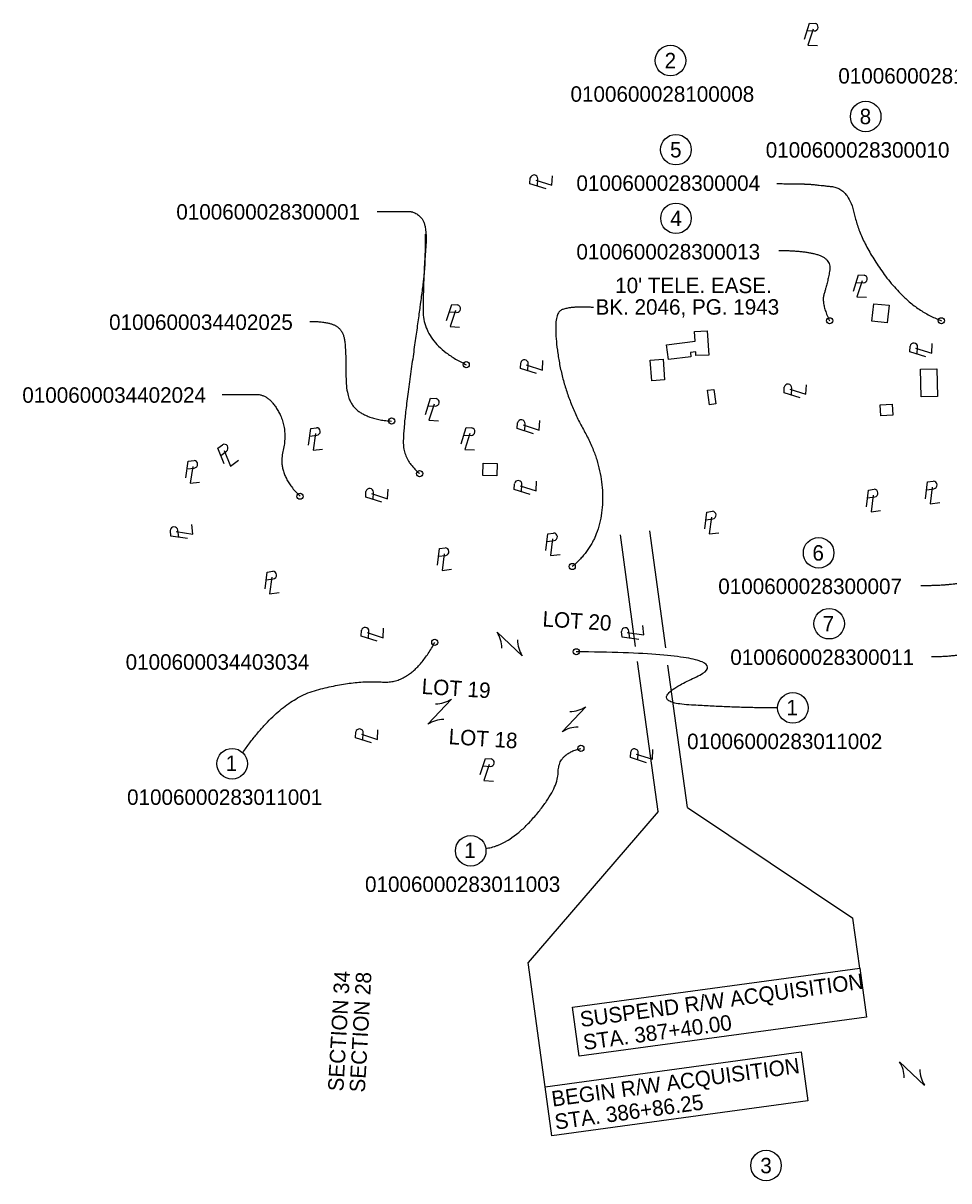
# Model space of a CAD drawing. Extents: x 1571291 to 1576333, y 700252 to 704384.
# Drawn here: x 1571291 to 1572970, y 701776 to 703874 of the extents above; entities that cross this region are included whole.
import ezdxf

# ---------------------------------------------------------------- set-up
doc = ezdxf.new("R2010")
doc.units = 0
doc.layers.add('RW_X_CL_100_Bearings', color=7, linetype='Continuous')
doc.layers.add('RW_X_CL_100_Cardinal_Points', color=7, linetype='Continuous')

msp = doc.modelspace()

# ---------------------------------------------------------------- linework, layer by layer
at = {"layer": 'RW_X_CL_100_Bearings'}
for p, q in [((1572402, 702743.9), (1572374.4, 702946.3)), ((1572456.6, 702741.8), (1572427.7, 702953.6)), ((1572442.7, 702445.1), (1572405.7, 702717)), ((1572496, 702452.4), (1572460.8, 702710.4)), ((1572442.7, 702445.1), (1572207.3, 702171.3)), ((1572496, 702452.4), (1572796.1, 702251.5)), ((1572808.5, 702161.1), (1572796.1, 702251.5)), ((1572238, 701946.1), (1572207.3, 702171.3))]:
    msp.add_line(p, q, dxfattribs=at)
for points in [[(1572830.8, 703333.7), (1572833.9, 703365.6), (1572861.7, 703362.9), (1572858.6, 703330.9)], [(1572461.9, 703264.3), (1572458.3, 703290.7), (1572509.8, 703297.8), (1572508.9, 703314.9), (1572531.9, 703316.5), (1572534.9, 703272.1), (1572511.5, 703271.8), (1572511.5, 703278.4), (1572501.4, 703277.2), (1572502.4, 703269.3)], [(1572431.6, 703226), (1572428.7, 703262.9), (1572451.8, 703264.7), (1572454.7, 703227.8)], [(1572919, 703246.9), (1572948.3, 703247.7), (1572949.6, 703197.4), (1572920.2, 703196.7)], [(1572532.4, 703208.7), (1572544.1, 703210.3), (1572547.7, 703183.8), (1572536, 703182.3)], [(1572846.8, 703162), (1572845.4, 703182.1), (1572867.5, 703183.6), (1572868.8, 703163.5)], [(1572150.4, 703053.5), (1572125.2, 703054.2), (1572125.8, 703076.6), (1572151, 703075.9)], [(1572125.8, 703076.6), (1572151, 703075.9), (1572150.4, 703053.5), (1572125.2, 703054.2)], [(1572287.7, 702090.2), (1572808.5, 702161.1), (1572820.6, 702072.4), (1572299.8, 702001.5)], [(1572238, 701946.1), (1572702.6, 702009.5), (1572714.7, 701920.8), (1572250.1, 701857.5)]]:
    msp.add_lwpolyline(points, close=True, dxfattribs=at)
for centre, radius in [((1572465.2, 703806.2), 27.7), ((1572819.4, 703704.9), 27.7), ((1572475.2, 703644.7), 27.7), ((1572475.3, 703520.3), 27.7), ((1572754, 703334.6), 5.6), ((1572956.7, 703334.6), 5.6), ((1572094.8, 703254.9), 5.6), ((1571959.5, 703152.9), 5.6), ((1572010.3, 703057.6), 5.6), ((1571793.5, 703016.6), 5.6), ((1572734, 702913.9), 27.7), ((1572287.1, 702889.2), 5.6), ((1572753.1, 702785.5), 27.7), ((1572037.8, 702751.7), 5.6), ((1572294.5, 702734.6), 5.6), ((1572687.3, 702632.8), 27.7), ((1572302.8, 702559.5), 5.6), ((1571670.2, 702531.7), 27.7), ((1572103, 702373.9), 27.7), ((1572638.6, 701803.3), 27.7)]:
    msp.add_circle(centre, radius, dxfattribs=at)
for points in [[(1572658.5, 703583.2), (1572706, 703582.9), (1572728.4, 703581.3), (1572789.1, 703574.2), (1572809.5, 703477.8), (1572899.4, 703355.8), (1572956.7, 703334.6)], [(1571933.3, 703532.6), (1571978.4, 703532.6), (1572003.9, 703532.6), (1572025, 703506.3), (1572016.7, 703413.1), (1572016.7, 703292.2), (1572094.8, 703254.9)], [(1572020.4, 703491.3), (1572020.2, 703451.5), (1572018.7, 703416.2), (1572003.9, 703309.4), (1571980.7, 703144.1), (1571980.7, 703082.5), (1572010.3, 703057.6)], [(1572661.7, 703462.1), (1572707.1, 703462.1), (1572758, 703446.5), (1572749.4, 703400.3), (1572738.3, 703366), (1572754, 703334.6)], [(1572325.6, 703358.7), (1572284, 703361.4), (1572250.6, 703346.7), (1572271.8, 703200.6), (1572345.8, 703069.2), (1572337.6, 702930.7), (1572287.1, 702889.2)], [(1571811, 703333.4), (1571845.6, 703333.4), (1571872.5, 703316.5), (1571876.8, 703276.1), (1571876.8, 703185.7), (1571923.9, 703154.4), (1571959.5, 703152.9)], [(1571652.4, 703201), (1571692.1, 703201), (1571737.3, 703201), (1571772.1, 703137.9), (1571752.4, 703055.6), (1571793.5, 703016.6)], [(1572939, 702725.9), (1572983.1, 702725.9), (1573049.4, 702743.7), (1573053.8, 702812.4), (1573062.7, 702941.2), (1573128.7, 703089.5), (1573148.7, 703138.8)], [(1572919.6, 702854.8), (1572979.9, 702854.8), (1573023.3, 702870.6), (1573035.2, 702906.9), (1573010.7, 703093.5), (1573044.7, 703124.2)], [(1571689.4, 702551.7), (1571755.6, 702646.5), (1571889.6, 702683.5), (1571997.2, 702676), (1572037.8, 702751.7)], [(1572659.6, 702632.8), (1572589.6, 702632.8), (1572411.5, 702643.6), (1572607.2, 702731.8), (1572294.5, 702734.6)], [(1572130.4, 702378.1), (1572173.8, 702384.1), (1572261.8, 702485.3), (1572261.8, 702549.7), (1572302.8, 702559.5)]]:
    msp.add_open_spline(points, degree=2, dxfattribs=at)
at = {"layer": 'RW_X_CL_100_Cardinal_Points'}
for p, q in [((1572713, 703860.5), (1572725.9, 703860)), ((1572720.7, 703853.9), (1572720.7, 703853.9)), ((1572223.9, 703578.8), (1572224.6, 703591.7)), ((1572230.6, 703586.5), (1572230.6, 703586.5)), ((1572802, 703404.2), (1572814.9, 703403.6)), ((1572809.7, 703397.6), (1572809.7, 703397.6)), ((1572064.5, 703350.7), (1572077.4, 703349.9)), ((1572072.1, 703344), (1572072.1, 703344)), ((1572912.9, 703274.1), (1572913.5, 703287.1)), ((1572919.5, 703281.9), (1572919.5, 703281.9)), ((1572206.6, 703243.8), (1572207.3, 703256.8)), ((1572213.2, 703251.5), (1572213.2, 703251.5)), ((1572684.8, 703199.6), (1572685.3, 703212.5)), ((1572691.3, 703207.3), (1572691.3, 703207.3)), ((1572025.7, 703180.6), (1572038.7, 703180)), ((1572033.4, 703174), (1572033.4, 703174)), ((1572201, 703134.9), (1572201.6, 703147.8)), ((1572207.6, 703142.6), (1572207.6, 703142.6)), ((1571811.1, 703125.5), (1571824, 703127.1)), ((1571819.9, 703120.3), (1571819.9, 703120.3)), ((1572090.6, 703127.5), (1572103.5, 703126.9)), ((1572098.3, 703120.9), (1572098.3, 703120.9)), ((1571649.6, 703090.6), (1571660, 703098.4)), ((1571659.7, 703090.4), (1571659.7, 703090.4)), ((1571588.6, 703066.3), (1571601.5, 703067.6)), ((1571597.2, 703060.9), (1571597.2, 703060.9)), ((1571926, 703010.7), (1571926.7, 703023.7)), ((1572195.3, 703024.7), (1572195.9, 703037.7)), ((1572201.9, 703032.4), (1572201.9, 703032.4)), ((1572930, 703028.3), (1572942.8, 703030.1)), ((1571932.7, 703018.4), (1571932.7, 703018.4)), ((1572822.8, 703013.7), (1572835.7, 703015.5)), ((1572831.6, 703008.6), (1572831.6, 703008.6)), ((1572938.8, 703023.2), (1572938.8, 703023.2)), ((1572529.4, 702973.7), (1572542.2, 702975.5)), ((1572538.2, 702968.6), (1572538.2, 702968.6)), ((1571573.3, 702942.1), (1571571.9, 702955)), ((1571578.6, 702950.8), (1571578.6, 702950.8)), ((1572241.4, 702934.5), (1572254.2, 702936.2)), ((1572250.2, 702929.4), (1572250.2, 702929.4)), ((1572044.7, 702907.7), (1572057.5, 702909.4)), ((1572053.5, 702902.6), (1572053.5, 702902.6)), ((1571732.1, 702865), (1571744.9, 702866.8)), ((1571740.8, 702860), (1571740.8, 702860)), ((1571917.6, 702758.8), (1571918.4, 702771.7)), ((1572391.5, 702759.3), (1572390, 702772.1)), ((1571924.3, 702766.4), (1571924.3, 702766.4)), ((1572196.4, 702727.5), (1572150.7, 702770.1)), ((1572396.8, 702768), (1572396.8, 702768)), ((1572173.5, 702748.8), (1572173.5, 702748.8)), ((1572025.4, 702603.1), (1572068, 702648.8)), ((1572046.7, 702625.9), (1572046.7, 702625.9)), ((1572269, 702589.5), (1572311.6, 702635.1)), ((1572290.3, 702612.3), (1572290.3, 702612.3)), ((1571907.3, 702574.5), (1571908.1, 702587.5)), ((1571914, 702582.2), (1571914, 702582.2)), ((1572406.1, 702538.5), (1572406.8, 702551.4)), ((1572412.8, 702546.1), (1572412.8, 702546.1)), ((1572125.5, 702527.6), (1572138.5, 702526.9)), ((1572133.2, 702520.9), (1572133.2, 702520.9)), ((1572926.3, 701948.7), (1572880.7, 701991.4)), ((1572903.5, 701970.1), (1572903.5, 701970.1))]:
    msp.add_line(p, q, dxfattribs=at)
for points in [[(1572708.1, 703844.8), (1572717.2, 703874.1), (1572727.5, 703873.6)], [(1572723.8, 703863.4), (1572714.7, 703834.2), (1572732.1, 703833.5)], [(1572239.6, 703573.8), (1572210.4, 703583.1), (1572210.9, 703593.4)], [(1572221.1, 703589.6), (1572250.2, 703580.2), (1572251.1, 703597.6)], [(1572797.1, 703388.5), (1572806.2, 703417.8), (1572816.5, 703417.3)], [(1572812.8, 703407.1), (1572803.6, 703377.9), (1572821, 703377.1)], [(1572059.2, 703335.1), (1572069, 703364.2), (1572079.3, 703363.5)], [(1572075.4, 703353.4), (1572065.5, 703324.4), (1572082.9, 703323.2)], [(1572928.6, 703269.2), (1572899.3, 703278.4), (1572899.8, 703288.7)], [(1572910, 703285), (1572939.2, 703275.7), (1572940, 703293.2)], [(1572222.3, 703238.8), (1572193.1, 703248.1), (1572193.6, 703258.4)], [(1572203.8, 703254.7), (1572232.9, 703245.2), (1572233.8, 703262.7)], [(1572700.5, 703194.7), (1572671.2, 703203.8), (1572671.6, 703214.1)], [(1572681.8, 703210.4), (1572711.1, 703201.3), (1572711.8, 703218.7)], [(1572020.8, 703164.9), (1572030, 703194.1), (1572040.3, 703193.6)], [(1572036.5, 703183.5), (1572027.2, 703154.3), (1572044.7, 703153.5)], [(1572216.6, 703129.9), (1572187.4, 703139.2), (1572188, 703149.5)], [(1572198.2, 703145.7), (1572227.3, 703136.3), (1572228.2, 703153.7)], [(1571808.9, 703109.2), (1571813, 703139.6), (1571823.3, 703140.8)], [(1571821.3, 703130.2), (1571817.1, 703099.8), (1571834.4, 703102)], [(1572085.6, 703111.8), (1572094.8, 703141.1), (1572105.2, 703140.6)], [(1572101.4, 703130.4), (1572092.1, 703101.2), (1572109.6, 703100.4)], [(1571655.7, 703075.3), (1571644.3, 703103.8), (1571652.6, 703110)], [(1571656.1, 703099.7), (1571667.4, 703071.3), (1571681.5, 703081.7)], [(1571586, 703050.1), (1571590.8, 703080.4), (1571601.1, 703081.4)], [(1571598.9, 703070.7), (1571593.9, 703040.5), (1571611.3, 703042.3)], [(1571941.7, 703005.7), (1571912.5, 703015), (1571913, 703025.4)], [(1571923.2, 703021.6), (1571952.3, 703012.1), (1571953.2, 703029.6)], [(1572211, 703019.7), (1572181.7, 703029), (1572182.3, 703039.3)], [(1572192.5, 703035.5), (1572221.6, 703026.1), (1572222.5, 703043.6)], [(1572820.8, 702997.4), (1572824.6, 703027.8), (1572834.8, 703029.2)], [(1572928, 703012), (1572931.7, 703042.4), (1572942, 703043.8)], [(1572940.1, 703033.1), (1572936.3, 703002.7), (1572953.6, 703005.1)], [(1572833, 703018.5), (1572829.1, 702988.1), (1572846.4, 702990.5)], [(1572527.4, 702957.4), (1572531.1, 702987.8), (1572541.4, 702989.2)], [(1571568.8, 702952.4), (1571599.1, 702947.7), (1571597.2, 702965.1)], [(1572539.5, 702978.5), (1572535.7, 702948.1), (1572553, 702950.5)], [(1571589.6, 702939.7), (1571559.3, 702944.2), (1571558.2, 702954.5)], [(1572239.4, 702918.1), (1572243.1, 702948.6), (1572253.3, 702949.9)], [(1572042.7, 702891.3), (1572046.4, 702921.8), (1572056.7, 702923.1)], [(1572251.5, 702939.2), (1572247.7, 702908.9), (1572265, 702911.2)], [(1572054.8, 702912.4), (1572051, 702882.1), (1572068.3, 702884.4)], [(1571730, 702848.7), (1571733.8, 702879.1), (1571744, 702880.5)], [(1571742.2, 702869.8), (1571738.3, 702839.5), (1571755.6, 702841.8)], [(1571933.3, 702753.7), (1571904.1, 702763.1), (1571904.7, 702773.5)], [(1571914.9, 702769.6), (1571944, 702760.1), (1571944.9, 702777.5)], [(1572386.9, 702769.5), (1572417.2, 702765.1), (1572415.1, 702782.5)], [(1572407.8, 702757), (1572377.4, 702761.2), (1572376.2, 702771.5)], [(1571923, 702569.5), (1571893.8, 702578.9), (1571894.4, 702589.2)], [(1571904.6, 702585.4), (1571933.7, 702575.8), (1571934.6, 702593.3)], [(1572120.4, 702511.9), (1572129.9, 702541.1), (1572140.2, 702540.5)], [(1572421.8, 702533.4), (1572392.6, 702542.8), (1572393.2, 702553.2)], [(1572403.3, 702549.3), (1572432.4, 702539.8), (1572433.4, 702557.2)], [(1572136.4, 702530.4), (1572126.8, 702501.3), (1572144.2, 702500.3)]]:
    msp.add_lwpolyline(points, dxfattribs=at)
for centre, radius, start, end in [((1572726.2, 703866.9), 6.9, 268.1189, 78.976), ((1572217.7, 703592), 6.9, 357.5123, 168.3695), ((1572815.2, 703410.5), 6.9, 267.9059, 78.763), ((1572077.8, 703356.7), 6.9, 266.6287, 77.4859), ((1572906.6, 703287.4), 6.9, 357.8437, 168.7008), ((1572200.4, 703257.1), 6.9, 357.5123, 168.3695), ((1572678.4, 703212.8), 6.9, 358.0993, 168.9564), ((1572038.9, 703186.9), 6.9, 267.79, 78.6471), ((1572194.7, 703148.1), 6.9, 357.5123, 168.3695), ((1571823.1, 703133.9), 6.9, 277.5709, 88.428), ((1572103.8, 703133.8), 6.9, 267.79, 78.6471), ((1571655.8, 703103.9), 6.9, 307.1309, 117.988), ((1571600.8, 703074.5), 6.9, 276.1234, 86.9805), ((1572189.1, 703038), 6.9, 357.5123, 168.3695), ((1571919.8, 703024), 6.9, 357.4809, 168.338), ((1572834.7, 703022.3), 6.9, 278.2323, 89.0894), ((1572941.9, 703036.9), 6.9, 278.2323, 89.0894), ((1572541.2, 702982.3), 6.9, 278.2323, 89.0894), ((1571565, 702954.2), 6.9, 6.707, 177.5641), ((1572253.2, 702943), 6.9, 278.2323, 89.0894), ((1572056.6, 702916.2), 6.9, 278.2323, 89.0894), ((1571743.9, 702873.6), 6.9, 278.2323, 89.0894), ((1571911.5, 702772), 6.9, 357.2712, 168.1283), ((1572383.1, 702771.3), 6.9, 7.2474, 178.1045), ((1572106, 702740.8), 53.4, 0.5738, 33.2163), ((1572241.1, 702756.8), 53.4, 180.5738, 213.2163), ((1572038.8, 702693.5), 53.4, 270.4947, 303.1372), ((1572282.4, 702679.8), 53.4, 270.4947, 303.1372), ((1572054.5, 702558.4), 53.4, 90.4947, 123.1372), ((1571901.2, 702587.8), 6.9, 357.2712, 168.1283), ((1572298.1, 702544.8), 53.4, 90.4947, 123.1372), ((1572399.9, 702551.7), 6.9, 357.2712, 168.1283), ((1572138.8, 702533.8), 6.9, 267.2712, 78.1283), ((1572836, 701962.2), 53.4, 0.4496, 33.0921), ((1572971, 701977.9), 53.4, 180.4496, 213.0921)]:
    msp.add_arc(centre, radius, start, end, dxfattribs=at)

# ---------------------------------------------------------------- texts
at = {"layer": 'RW_X_CL_100_Bearings'}
for s, p in [('2', (1572454.7, 703792.2)), ('0100600028101017', (1572769.7, 703764.6)), ('0100600028100008', (1572284, 703731.6)), ('8', (1572808.4, 703690.9)), ('5', (1572464.5, 703630.7)), ('0100600028300010', (1572638.1, 703630.3)), ('0100600028300004', (1572294.7, 703570.1)), ('0100600028300001', (1571569, 703518)), ('4', (1572465, 703506.3)), ('0100600028300013', (1572294.7, 703445.7)), ("10' TELE. EASE.", (1572365, 703384.7)), ('BK. 2046, PG. 1943', (1572329.4, 703345.7)), ('0100600034402025', (1571447.1, 703318)), ('0100600034402024', (1571289.7, 703186)), ('6', (1572722.8, 702899.9)), ('0100600028300007', (1572552, 702839.3)), ('7', (1572741.3, 702771.5)), ('0100600034403034', (1571477.1, 702702.1)), ('0100600028300011', (1572573.8, 702710.8)), ('1', (1572675.5, 702619.5)), ('01006000283011002', (1572495.4, 702558.2)), ('1', (1571658.5, 702518.5)), ('01006000283011001', (1571479.7, 702457.1)), ('1', (1572091.2, 702360.6)), ('01006000283011003', (1571911.3, 702299.3)), ('3', (1572628.2, 701789.3))]:
    msp.add_text(s, height=28, dxfattribs=at).set_placement(p)
for s, rotation, p in [('LOT 20', 356.322, (1572232.6, 702780.6)), ('LOT 19', 356.322, (1572013.4, 702658.3)), ('LOT 18', 356.322, (1572062.3, 702567.3)), ('SECTION 34', 86.8002, (1571871.9, 701937.2)), ('SECTION 28', 86.8002, (1571910.9, 701935.3)), ('SUSPEND R/W ACQUISITION', 7.7613, (1572303.2, 702054.2)), ('STA. 387+40.00', 7.7613, (1572308.8, 702012.6)), ('BEGIN R/W ACQUISITION', 7.7613, (1572251.6, 701910)), ('STA. 386+86.25', 7.7613, (1572257.3, 701868.4))]:
    msp.add_text(s, height=28, rotation=rotation, dxfattribs=at).set_placement(p)

doc.saveas('drawing.dxf')
